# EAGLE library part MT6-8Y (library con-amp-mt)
AMP MT6 CONNECTOR
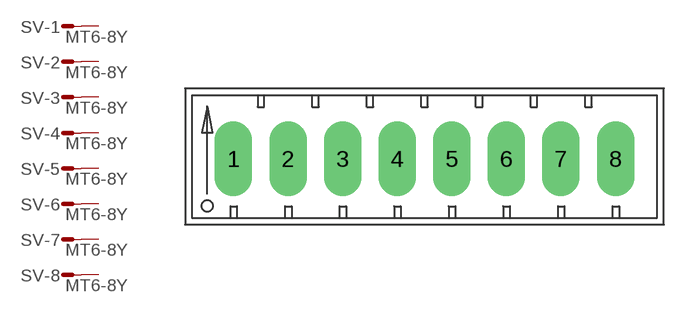
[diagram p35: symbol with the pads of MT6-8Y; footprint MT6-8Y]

Designator prefix SV; gates -1=MA -2=MA -3=MA -4=MA -5=MA -6=MA -7=MA -8=MA

## MT6-8Y (OC_FARNELL: unknown; OC_NEWARK: unknown)  [MT6-8Y]
1  -1:S  pas
2  -2:S  pas
3  -3:S  pas
4  -4:S  pas
5  -5:S  pas
6  -6:S  pas
7  -7:S  pas
8  -8:S  pas

## Footprint MT6-8Y (pad centres in mm)
AMP MT6 CONNECTOR
drill 1.803 long: 1 -13.868,0; 2 -9.906,0; 3 -5.944,0; 4 -1.981,0; 5 1.981,0; 6 5.944,0; 7 9.906,0; 8 13.868,0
